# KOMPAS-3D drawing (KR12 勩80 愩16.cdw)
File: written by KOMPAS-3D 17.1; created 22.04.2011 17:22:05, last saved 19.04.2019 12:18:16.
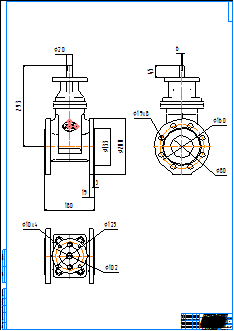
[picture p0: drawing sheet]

Title block, sheet 1: name: KR12 Ду80 Ру16; material: Внимание! Данный продукт является объектом авторского права ООО «Торговый Дом АДЛ». / Запрещается изменение, копирование, распространение / (в том числе путем копирования на другие сайты и ресурсы в Интернете) / или любое иное использование информации и объектов без предварительного / согласия правообладателя (ООО «Торговый Дом АДЛ»).; scale: 1:1; sheets: 1; organisation: ООО "Торговый дом АДЛ"; sheet format: A0; stored path: \\adlc.lan\data\АДЛ_ПКД\3D-модели\ADL production\Клиновые задвижки серии KR ГРАНАР\Клиновые задвижки KR12\KOMPAS 2D\KR12 Ду80 Ру16.cdw

Views: Спереди 4, Проекционный вид 5, Проекционный вид 6
Dimensions and other numbers on the sheet: 200; 133; 180; 3; 19; 293; 20; 10; 125; 102; 160; 80; 45; 6; 1:1; 1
